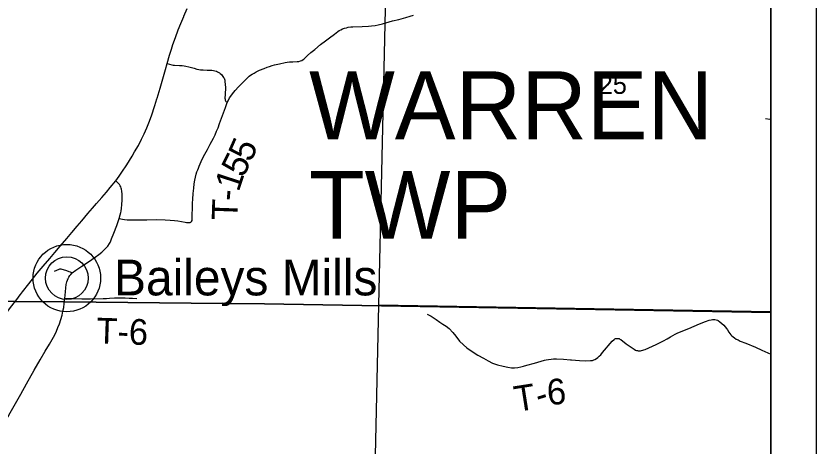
# Model space of a CAD drawing. Extents: x 0 to 34, y 0 to 22.
# Drawn here: x 7.235 to 9, y 18.929 to 19.879 of the extents above; entities that cross this region are included whole.
import ezdxf

# ---------------------------------------------------------------- set-up
doc = ezdxf.new("R2010")
doc.units = 0
for name, color, linetype in [('GM_X_Corporation', 7, 'Continuous'), ('GM_X_Section_Text', 7, 'Continuous'), ('GM_X_State_Route', 7, 'Continuous'), ('GM_X_Township_Road', 7, 'Continuous'), ('GM_X_Township_Road_Text', 7, 'Continuous'), ('GM_X_Township_Text', 7, 'Continuous'), ('GM_X_Unincorporated', 7, 'Continuous'), ('GM_X_Unincorporated_Location', 7, 'Continuous'), ('GM_X_Unincorporated_Text', 7, 'Continuous'), ('SH_Data', 7, 'Continuous')]:
    doc.layers.add(name, color=color, linetype=linetype)

msp = doc.modelspace()

# ---------------------------------------------------------------- linework, layer by layer
at = {"layer": 'GM_X_Corporation'}
for points in [[(7.1227, 14.1), (8.9, 14.1), (8.9, 20.9), (7.231, 20.9), (7.2244, 20.2649), (7.1982, 19.2496), (7.1981, 19.2461), (7.1974, 19.2018), (7.1957, 19.0991), (7.1992, 18.9556), (7.197, 18.9465), (7.1949, 18.8464), (7.1846, 18.5133), (7.1817, 18.3306), (7.1804, 18.2238), (7.1572, 17.4131), (7.1504, 16.6562), (7.1434, 16.3848), (7.1318, 15.4937)], [(8.9, 19.2243), (8.9, 20.9), (7.231, 20.9), (7.2244, 20.2649), (7.1982, 19.2496), (7.2323, 19.2489), (7.3421, 19.2478), (7.6914, 19.2442), (7.7835, 19.2432)], [(8.9, 19.2258), (8.9, 20.2429), (8.0575, 20.2545), (8.0347, 19.2404)], [(8.9, 18.393), (8.9, 19.2258), (8.0347, 19.2404), (8.0161, 18.4109)]]:
    msp.add_lwpolyline(points, close=True, dxfattribs=at)
at = {"layer": 'GM_X_State_Route'}
for points in [[(7.605, 19.8782), (7.6054, 19.8791), (7.6127, 19.8956)], [(7.5458, 19.6962), (7.5463, 19.6981), (7.5528, 19.7201), (7.5603, 19.746), (7.5647, 19.7611), (7.5685, 19.7741), (7.5739, 19.7926), (7.5778, 19.806), (7.5811, 19.8167), (7.5866, 19.8319), (7.5928, 19.8485), (7.5983, 19.8625), (7.605, 19.8782)], [(7.4549, 19.5154), (7.4623, 19.5257), (7.4685, 19.5342), (7.4793, 19.5506), (7.4854, 19.5603), (7.4909, 19.5694), (7.4966, 19.579), (7.5048, 19.5935), (7.5118, 19.6073), (7.5175, 19.6191), (7.5232, 19.6322), (7.5276, 19.6431), (7.5335, 19.6587), (7.5412, 19.6813), (7.5458, 19.6962)], [(7.2387, 19.2562), (7.2418, 19.2602), (7.2449, 19.2643), (7.2491, 19.2698), (7.2629, 19.288), (7.2818, 19.3114), (7.2946, 19.3265), (7.3092, 19.3439), (7.3204, 19.357), (7.3323, 19.3711), (7.3468, 19.3882), (7.3578, 19.4011), (7.3698, 19.4152), (7.38, 19.4271), (7.3934, 19.4431), (7.4037, 19.4548), (7.4125, 19.4649), (7.424, 19.4781), (7.4343, 19.4899), (7.443, 19.5007), (7.4549, 19.5154)], [(7.3427, 19.2553), (7.3441, 19.2698), (7.3448, 19.2791), (7.3458, 19.2862), (7.3472, 19.292), (7.3484, 19.296), (7.35, 19.2996), (7.3515, 19.3027), (7.3534, 19.3058), (7.3555, 19.3084), (7.3587, 19.3117), (7.3667, 19.3181), (7.3802, 19.3271), (7.3945, 19.3364), (7.4093, 19.3466), (7.4178, 19.3526), (7.4239, 19.3574), (7.4288, 19.3619), (7.4332, 19.3662), (7.4372, 19.3711), (7.4409, 19.3765), (7.4424, 19.3791), (7.4441, 19.3824), (7.4458, 19.3868), (7.4508, 19.3997), (7.4575, 19.4169), (7.4606, 19.4255), (7.4628, 19.4317), (7.465, 19.4401), (7.4661, 19.4451), (7.4667, 19.4485), (7.4676, 19.4545), (7.4684, 19.4619), (7.4689, 19.473), (7.469, 19.4856), (7.4686, 19.4924), (7.4679, 19.4965), (7.4671, 19.4992), (7.4661, 19.5019), (7.465, 19.5041), (7.4631, 19.5072), (7.4609, 19.5097), (7.459, 19.5118), (7.4569, 19.5137), (7.4549, 19.5154)], [(7.1976, 19.2012), (7.2163, 19.2264), (7.2257, 19.2392), (7.2387, 19.2562)], [(7.2, 18.9571), (7.2002, 18.9582), (7.2019, 18.9631), (7.2043, 18.969), (7.2067, 18.9745), (7.2092, 18.9796), (7.2221, 19.0025), (7.2453, 19.0437), (7.2581, 19.0668), (7.2751, 19.0967), (7.2881, 19.1201), (7.299, 19.1387), (7.3085, 19.1542), (7.3147, 19.1649), (7.3202, 19.175), (7.3242, 19.1834), (7.3275, 19.1912), (7.3306, 19.1997), (7.3336, 19.2087), (7.3364, 19.2185), (7.3385, 19.2275), (7.3402, 19.2356), (7.3415, 19.2442), (7.3427, 19.2553)]]:
    msp.add_lwpolyline(points, dxfattribs=at)
at = {"layer": 'GM_X_Township_Road'}
for points in [[(7.7011, 19.6885), (7.7028, 19.692), (7.7061, 19.6985), (7.7086, 19.7026), (7.7122, 19.7073), (7.7186, 19.7146), (7.7261, 19.723), (7.7426, 19.74), (7.7492, 19.7461), (7.7521, 19.7484), (7.7556, 19.7508), (7.76, 19.7533), (7.7651, 19.756), (7.7724, 19.7595), (7.7821, 19.7636), (7.7887, 19.7662), (7.7939, 19.7681), (7.8002, 19.77), (7.805, 19.7712), (7.816, 19.7739), (7.829, 19.7768), (7.8335, 19.7775), (7.8385, 19.7778), (7.8459, 19.7782), (7.8549, 19.7786), (7.8589, 19.779), (7.8625, 19.7802), (7.8653, 19.7814), (7.8685, 19.7833), (7.8704, 19.7849), (7.8783, 19.792), (7.8856, 19.7986), (7.8939, 19.8055), (7.9069, 19.8162), (7.9178, 19.8245), (7.9267, 19.8314), (7.9373, 19.8393), (7.9453, 19.8453), (7.9479, 19.847), (7.9517, 19.849), (7.9556, 19.8508), (7.9597, 19.8523), (7.9638, 19.8535), (7.968, 19.8545), (7.9734, 19.8553), (7.9779, 19.8556), (7.9986, 19.8561), (8.0127, 19.8569), (8.0192, 19.8575), (8.0274, 19.8585), (8.0337, 19.8598), (8.0432, 19.8622), (8.0659, 19.8684), (8.0798, 19.872), (8.0952, 19.8759), (8.1043, 19.8787), (8.1118, 19.8812)], [(7.5685, 19.7741), (7.5786, 19.7712), (7.5814, 19.7707), (7.5849, 19.7704), (7.5956, 19.7701), (7.6015, 19.7698), (7.6058, 19.7694), (7.6098, 19.7686), (7.6165, 19.7672), (7.622, 19.7657), (7.6277, 19.7641), (7.6336, 19.7621), (7.638, 19.761), (7.6417, 19.7605), (7.6476, 19.7601), (7.6564, 19.7598), (7.6667, 19.7596), (7.6708, 19.7592), (7.6737, 19.7586), (7.6769, 19.7575), (7.6797, 19.756), (7.6836, 19.7536), (7.685, 19.7525), (7.6881, 19.7498), (7.6914, 19.7456), (7.6926, 19.7438), (7.6938, 19.7417), (7.6947, 19.74), (7.6955, 19.7376), (7.696, 19.7346), (7.6967, 19.7282), (7.6969, 19.7211), (7.6966, 19.7057), (7.696, 19.6975), (7.6961, 19.6956), (7.6964, 19.6937), (7.6968, 19.6919), (7.6979, 19.6905), (7.6992, 19.6894), (7.7011, 19.6885)], [(7.6208, 19.4239), (7.6222, 19.4253), (7.6232, 19.4273), (7.6237, 19.4294), (7.6239, 19.4328), (7.6241, 19.4623), (7.6243, 19.4661), (7.6248, 19.4746), (7.6261, 19.4874), (7.6273, 19.4994), (7.6283, 19.5084), (7.6296, 19.5165), (7.631, 19.5233), (7.6327, 19.53), (7.6342, 19.5349), (7.6357, 19.5392), (7.6373, 19.5433), (7.6391, 19.5476), (7.6434, 19.5576), (7.6481, 19.5675), (7.6516, 19.5742), (7.6573, 19.5848), (7.6633, 19.596), (7.6705, 19.6095), (7.6742, 19.6171), (7.6776, 19.6249), (7.6806, 19.6326), (7.6839, 19.6418), (7.6884, 19.6539), (7.6926, 19.6653), (7.6969, 19.6771), (7.7011, 19.6885)], [(8.8884, 19.6533), (8.898, 19.6517), (8.9, 19.6513)], [(7.4628, 19.4317), (7.4701, 19.4303), (7.4745, 19.4298), (7.4804, 19.4294), (7.5061, 19.4293), (7.5238, 19.4294), (7.544, 19.4296), (7.5637, 19.4291), (7.5749, 19.4284), (7.5848, 19.4275), (7.592, 19.4266), (7.6003, 19.4251), (7.6078, 19.4238), (7.6112, 19.4233), (7.615, 19.4229), (7.6173, 19.4229), (7.619, 19.4231), (7.6208, 19.4239)], [(7.3196, 19.316), (7.33, 19.3203), (7.3318, 19.3209), (7.3338, 19.321), (7.3359, 19.3203), (7.3389, 19.3192), (7.3463, 19.3169), (7.3515, 19.3152), (7.3541, 19.3144), (7.356, 19.3134), (7.3587, 19.3117)], [(7.3427, 19.2553), (7.3641, 19.255), (7.3798, 19.2548), (7.3993, 19.2547), (7.4271, 19.2551), (7.4342, 19.2555), (7.4413, 19.2561), (7.4523, 19.2567), (7.4754, 19.2565), (7.4844, 19.2562), (7.4919, 19.2559), (7.5016, 19.2552)], [(8.1419, 19.2205), (8.1512, 19.216), (8.1618, 19.2089), (8.1697, 19.2034), (8.1768, 19.1989), (8.1841, 19.1943), (8.1908, 19.189), (8.1985, 19.1803), (8.2052, 19.1719), (8.2134, 19.1614), (8.2221, 19.1527), (8.2296, 19.1465), (8.2414, 19.1386), (8.2542, 19.13), (8.2662, 19.1233), (8.2766, 19.1173), (8.2861, 19.1128), (8.2972, 19.1087), (8.3097, 19.1056), (8.3197, 19.1036), (8.328, 19.1025), (8.3344, 19.1021), (8.3422, 19.1029), (8.3487, 19.1043), (8.3547, 19.1058), (8.3619, 19.1078), (8.3788, 19.1126), (8.4013, 19.1191), (8.4044, 19.1198), (8.4098, 19.1208), (8.4153, 19.1215), (8.4209, 19.1219), (8.4273, 19.1221), (8.4432, 19.1214), (8.458, 19.12), (8.4605, 19.1198), (8.4782, 19.1183), (8.4912, 19.1179), (8.5021, 19.1181), (8.5068, 19.1187), (8.5095, 19.1195), (8.5121, 19.1205), (8.516, 19.1229), (8.5186, 19.1249), (8.5216, 19.1276), (8.525, 19.1312), (8.529, 19.1363), (8.55, 19.161), (8.5544, 19.1649), (8.556, 19.1659), (8.5578, 19.1666), (8.5597, 19.167), (8.5616, 19.1672), (8.5636, 19.167), (8.5655, 19.1666), (8.5674, 19.1658), (8.5692, 19.1647), (8.5815, 19.1554), (8.5941, 19.1463), (8.5989, 19.1431), (8.6019, 19.1415), (8.6042, 19.1406), (8.6062, 19.1401), (8.6078, 19.1399), (8.6103, 19.1397), (8.6127, 19.1399), (8.6151, 19.1403), (8.6231, 19.1427), (8.6477, 19.154), (8.6578, 19.1588), (8.6635, 19.1617), (8.6717, 19.1663), (8.679, 19.1708), (8.6839, 19.1736), (8.6889, 19.1762), (8.6939, 19.1786), (8.6991, 19.1808), (8.7193, 19.1892), (8.7428, 19.1993), (8.7561, 19.2045), (8.7645, 19.2073), (8.7687, 19.2085), (8.7717, 19.209), (8.7771, 19.2088), (8.7798, 19.2083), (8.7824, 19.2075), (8.7844, 19.2065), (8.788, 19.204), (8.7965, 19.1966), (8.7996, 19.193), (8.8025, 19.1892), (8.805, 19.1858), (8.8079, 19.1813), (8.81, 19.1783), (8.8123, 19.1754), (8.8144, 19.173), (8.8169, 19.1707), (8.8203, 19.1681), (8.8242, 19.1657), (8.8279, 19.1637), (8.8328, 19.1614), (8.8453, 19.1563), (8.8663, 19.1476), (8.8802, 19.1412), (8.9, 19.132)]]:
    msp.add_lwpolyline(points, dxfattribs=at)
at = {"layer": 'GM_X_Township_Text'}
for points in [[(7.231, 20.9), (8.9, 20.9), (8.9, 19.2243)], [(7.1227, 14.1), (8.9, 14.1), (8.9, 19.2243), (7.7835, 19.2432), (7.6914, 19.2442), (7.3421, 19.2478), (7.2323, 19.2489), (7.1982, 19.2496)]]:
    msp.add_lwpolyline(points, dxfattribs=at)
at = {"layer": 'GM_X_Unincorporated'}
for radius in [0.0744, 0.0472]:
    msp.add_circle((7.347, 19.3004), radius, dxfattribs=at)
at = {"layer": 'GM_X_Unincorporated_Location'}
msp.add_line((7.347, 19.3004), (7.347, 19.3004), dxfattribs=at)
at = {"layer": 'SH_Data'}
for p, q in [((9, 21), (9, 14)), ((8.9, 20.9), (8.9, 14.1))]:
    msp.add_line(p, q, dxfattribs=at)

# ---------------------------------------------------------------- texts
at = {"layer": 'GM_X_Section_Text'}
msp.add_text('25', height=0.04186, rotation=0, dxfattribs=at).set_placement((8.5205, 19.7073))
at = {"layer": 'GM_X_Township_Road_Text'}
for s, height, rotation, p in [('5', 0.0568, 66.2308, (7.753, 19.5543)), ('5', 0.0568, 63.4698, (7.7361, 19.5203)), ('1', 0.0568, 72.0012, (7.7262, 19.4891)), ('-', 0.0568, 84.7625, (7.7247, 19.4691)), ('T', 0.0568, 87.9896, (7.7233, 19.4275)), ('T-6', 0.05682, 358.0919, (7.4114, 19.1562)), ('T', 0.0568, 8.9762, (8.3387, 19.0046)), ('6', 0.0568, 4.6573, (8.4084, 19.0196)), ('-', 0.0568, 17.2386, (8.3893, 19.0133))]:
    msp.add_text(s, height=height, rotation=rotation, dxfattribs=at).set_placement(p)
at = {"layer": 'GM_X_Township_Text'}
for s, p in [('WARREN', (7.8815, 19.6072)), ('TWP', (7.8815, 19.3872))]:
    msp.add_text(s, height=0.15, rotation=0, dxfattribs=at).set_placement(p)
at = {"layer": 'GM_X_Unincorporated_Text'}
msp.add_text('Baileys Mills', height=0.078977, rotation=0, dxfattribs=at).set_placement((7.4513, 19.2622))

doc.saveas('drawing.dxf')
